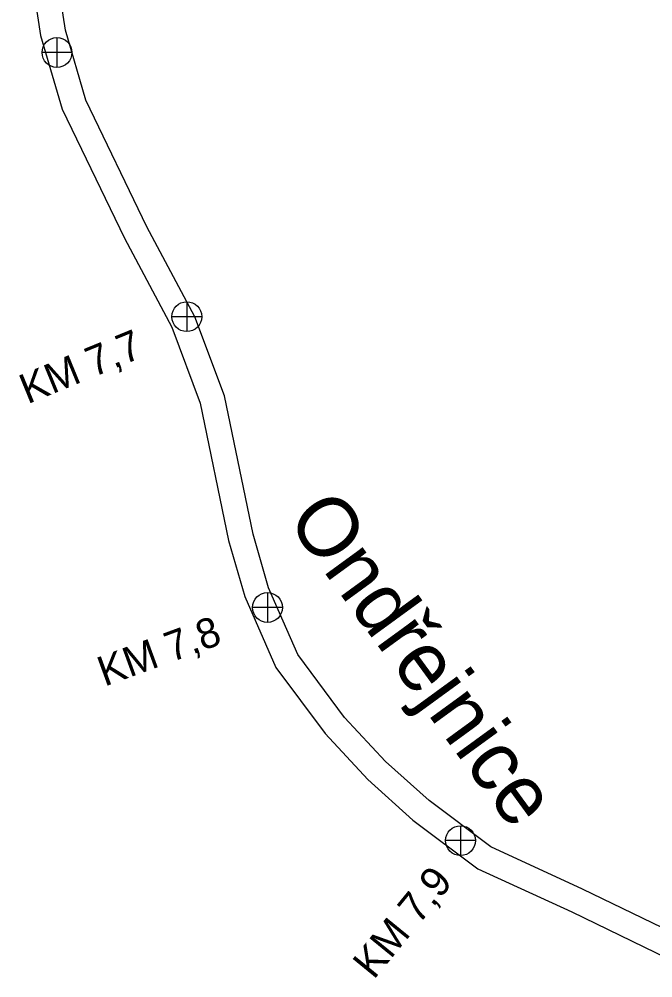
# Model space of a CAD drawing. Extents: x -478232 to -472707, y -1118753 to -1113967.
# Drawn here: x -476576.5 to -476364.6, y -1116200.4 to -1115879.6 of the extents above; entities that cross this region are included whole.
import ezdxf

# ---------------------------------------------------------------- set-up
doc = ezdxf.new("R2010")
doc.units = 0
doc.layers.add('staničení toku', color=7, linetype='Continuous')
doc.layers.add('vodní plochy', color=7, linetype='Continuous')

msp = doc.modelspace()

# ---------------------------------------------------------------- linework, layer by layer
at = {"layer": 'staničení toku'}
for p, q in [((-476563.839, -1115885.795), (-476563.839, -1115895.795)), ((-476558.839, -1115890.795), (-476568.839, -1115890.795)), ((-476520.422, -1115974.182), (-476520.422, -1115984.182)), ((-476515.422, -1115979.182), (-476525.422, -1115979.182)), ((-476493.455, -1116071.473), (-476493.455, -1116081.473)), ((-476488.455, -1116076.473), (-476498.455, -1116076.473)), ((-476428.891, -1116149.502), (-476428.891, -1116159.502)), ((-476423.891, -1116154.502), (-476433.891, -1116154.502))]:
    msp.add_line(p, q, dxfattribs=at)
for centre in [(-476563.839, -1115890.795), (-476520.422, -1115979.182), (-476493.455, -1116076.473), (-476428.891, -1116154.502)]:
    msp.add_circle(centre, 5, dxfattribs=at)
at = {"layer": 'vodní plochy'}
for points in [[(-476573.38, -1115858.669), (-476569.313, -1115885.12), (-476562.082, -1115909.761), (-476541.293, -1115952.896), (-476525.473, -1115982.744), (-476515.979, -1116008.073), (-476506.486, -1116054.025), (-476501.063, -1116072.79), (-476490.67, -1116096.526), (-476474.175, -1116118.681), (-476459.94, -1116134.054), (-476444.8, -1116147.619), (-476423.109, -1116163.897)], [(-476347.924, -1116190.183), (-476388.083, -1116170.718), (-476418.752, -1116156.59), (-476439.429, -1116141.074), (-476454.001, -1116128.018), (-476467.661, -1116113.266), (-476483.308, -1116092.249), (-476493.091, -1116069.906), (-476498.268, -1116051.992), (-476507.828, -1116005.719), (-476517.743, -1115979.265), (-476533.743, -1115949.077), (-476554.161, -1115906.714), (-476561.038, -1115883.278), (-476564.915, -1115858.06)], [(-476423.109, -1116163.897), (-476391.698, -1116178.366), (-476351.584, -1116197.809)]]:
    msp.add_lwpolyline(points, dxfattribs=at)

# ---------------------------------------------------------------- texts
at = {"layer": 'staničení toku'}
for s, rotation, p in [('KM 7,7', 22.29233, (-476573.7, -1116008.528)), ('KM 7,8', 20.07661, (-476547.941, -1116103.009)), ('KM 7,9', 50.77308, (-476457.906, -1116201.253))]:
    msp.add_text(s, height=10, rotation=rotation, dxfattribs=at).set_placement(p)
at = {"layer": 'vodní plochy'}
msp.add_text('Ondřejnice', height=20, rotation=306.08779, dxfattribs=at).set_placement((-476487.384, -1116047.089))

doc.saveas('drawing.dxf')
